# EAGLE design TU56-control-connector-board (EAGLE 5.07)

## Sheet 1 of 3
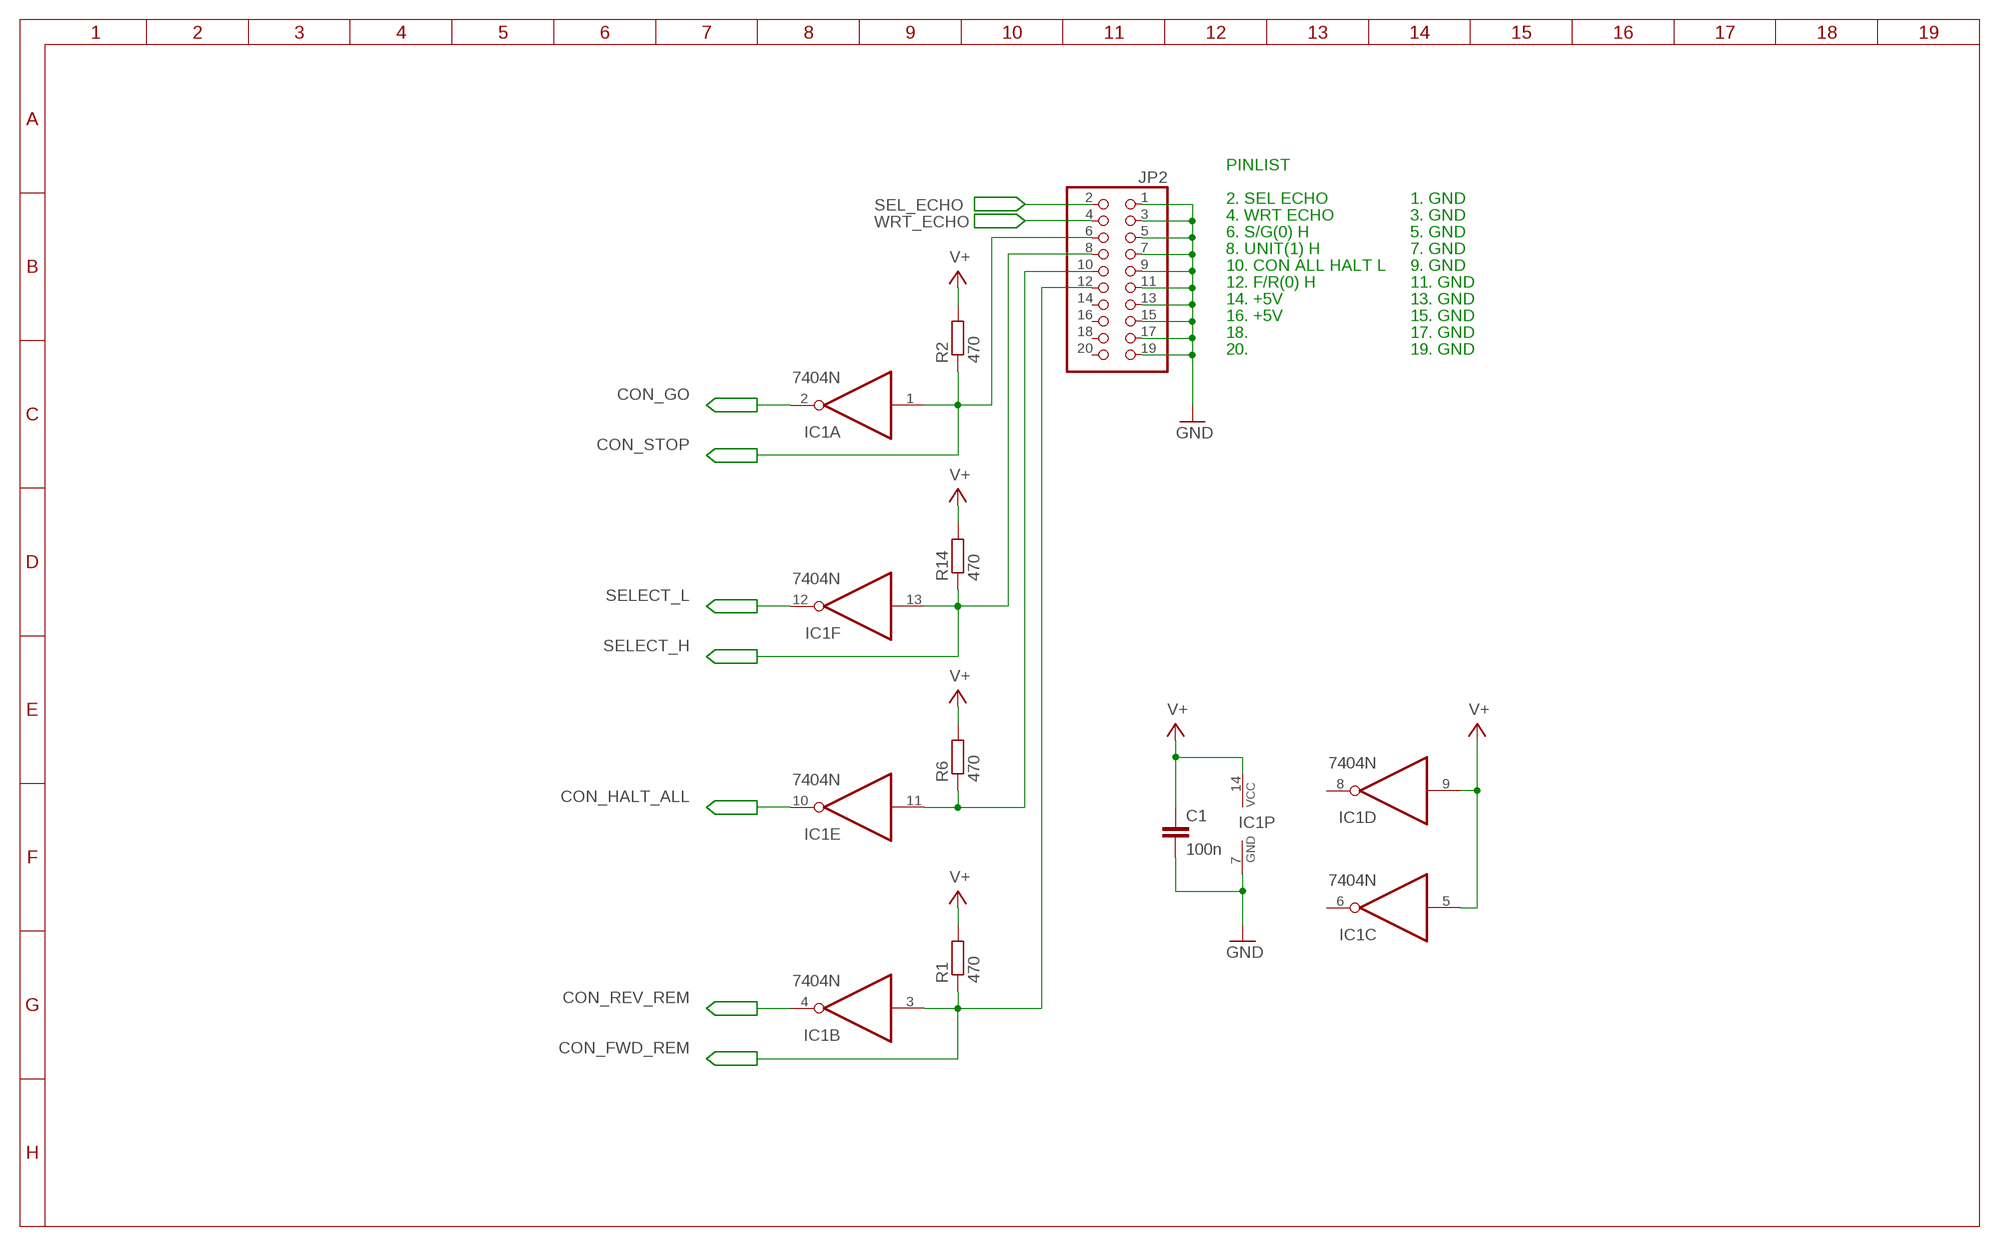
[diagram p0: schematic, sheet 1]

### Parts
C1  100n  C5/3.5  [C5B3.5]
IC1  7404N  [DIL14]
JP2  PINHD-2X10/90-FRAMED  [2Z10/90-FRAMED]
R1  470  R-EU_0207/10  [0207/10]
R2  470  R-EU_0207/10  [0207/10]
R6  470  R-EU_0207/10  [0207/10]
R14  470  R-EU_0207/10  [0207/10]

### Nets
CON_FWD_REM: IC1.3(B:I) JP2.12 R1.1 ; also sheet 3
CON_GO: IC1.2(A:O) ; also sheet 3
CON_HALT_ALL: IC1.10(E:O) ; also sheet 3
CON_REV_REM: IC1.4(B:O) ; also sheet 3
CON_STOP: IC1.1(A:I) JP2.6 R2.1 ; also sheet 3
GND: C1.2 IC1.7(P:GND) JP2.1 JP2.3 JP2.5 JP2.7 JP2.9 JP2.11 JP2.13 JP2.15 JP2.17 JP2.19 ; also sheet 3
N$4: IC1.11(E:I) JP2.10 R6.1
SEL_ECHO: JP2.2 ; also sheet 3
SELECT_H: IC1.13(F:I) JP2.8 R14.1 ; also sheet 2
SELECT_L: IC1.12(F:O) ; also sheet 2
V+: C1.1 IC1.5(C:I) IC1.9(D:I) IC1.14(P:VCC) R1.2 R2.2 R6.2 R14.2 ; also sheet 2,3
WRT_ECHO: JP2.4 ; also sheet 3
Unconnected: IC1.6(C:O) IC1.8(D:O) JP2.14 JP2.16 JP2.18 JP2.20

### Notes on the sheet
- PINLIST
- 2. SEL ECHO | 1. GND
- 4. WRT ECHO | 3. GND
- 6. S/G(0) H | 5. GND
- 8. UNIT(1) H | 7. GND
- 10. CON ALL HALT L | 9. GND
- 12. F/R(0) H | 11. GND
- 14. +5V | 13. GND
- 16. +5V | 15. GND
- 18. | 17. GND
- 20. | 19. GND

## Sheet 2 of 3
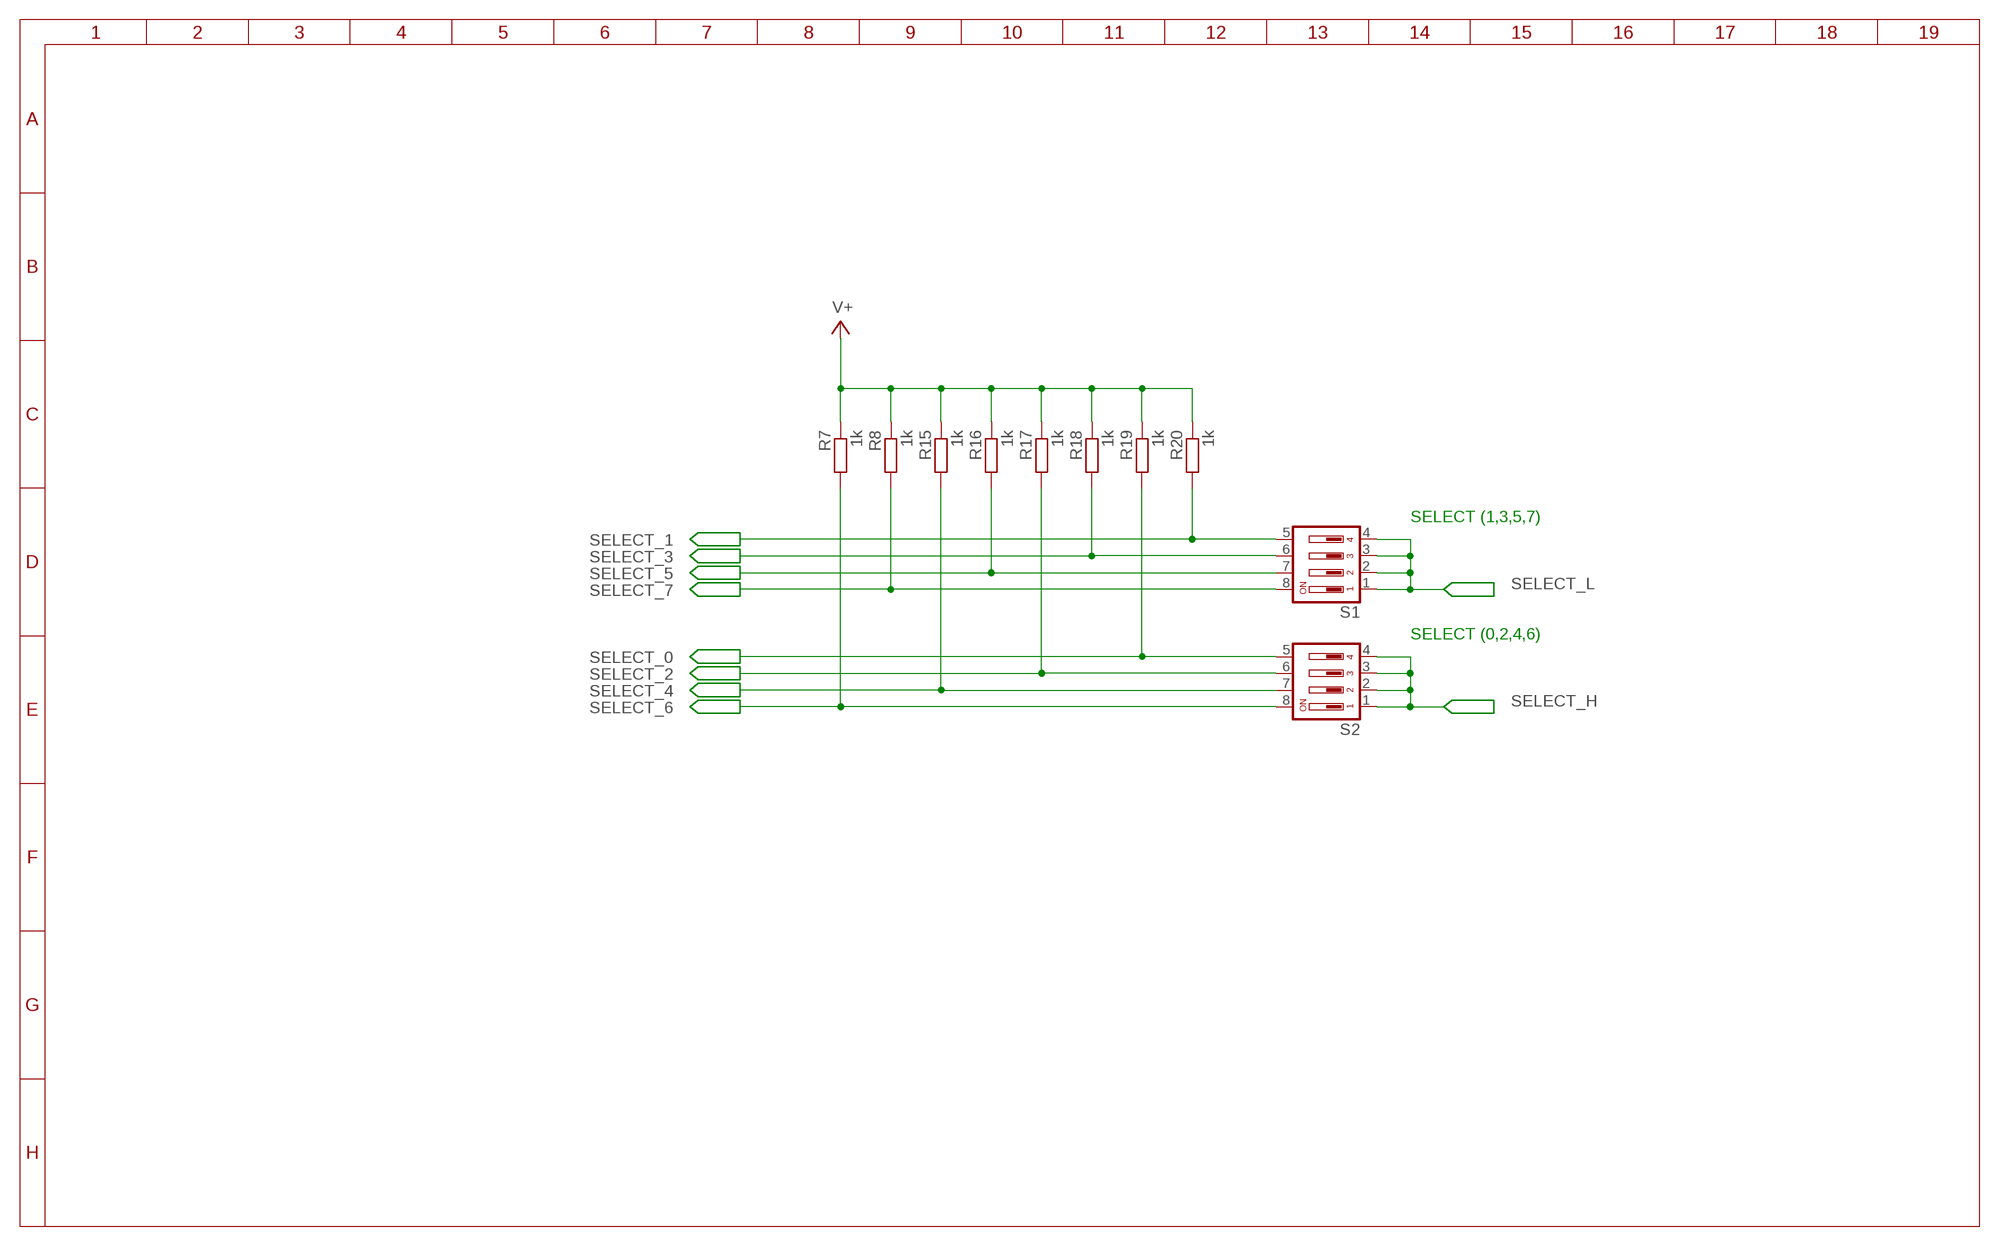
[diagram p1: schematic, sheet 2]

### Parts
R7  1k  R-EU_0207/10  [0207/10]
R8  1k  R-EU_0207/10  [0207/10]
R15  1k  R-EU_0207/10  [0207/10]
R16  1k  R-EU_0207/10  [0207/10]
R17  1k  R-EU_0207/10  [0207/10]
R18  1k  R-EU_0207/10  [0207/10]
R19  1k  R-EU_0207/10  [0207/10]
R20  1k  R-EU_0207/10  [0207/10]
S1  DIP04YL  [DIP04YL]
S2  DIP04YL  [DIP04YL]

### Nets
SELECT_0: R19.2 S2.5 ; also sheet 3
SELECT_1: R20.2 S1.5 ; also sheet 3
SELECT_2: R17.2 S2.6 ; also sheet 3
SELECT_3: R18.2 S1.6 ; also sheet 3
SELECT_4: R15.2 S2.7 ; also sheet 3
SELECT_5: R16.2 S1.7 ; also sheet 3
SELECT_6: R7.2 S2.8 ; also sheet 3
SELECT_7: R8.2 S1.8 ; also sheet 3
SELECT_H: S2.1 S2.2 S2.3 S2.4 ; also sheet 1
SELECT_L: S1.1 S1.2 S1.3 S1.4 ; also sheet 1
V+: R7.1 R8.1 R15.1 R16.1 R17.1 R18.1 R19.1 R20.1 ; also sheet 1,3

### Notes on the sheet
- SELECT (1,3,5,7)
- SELECT (0,2,4,6)

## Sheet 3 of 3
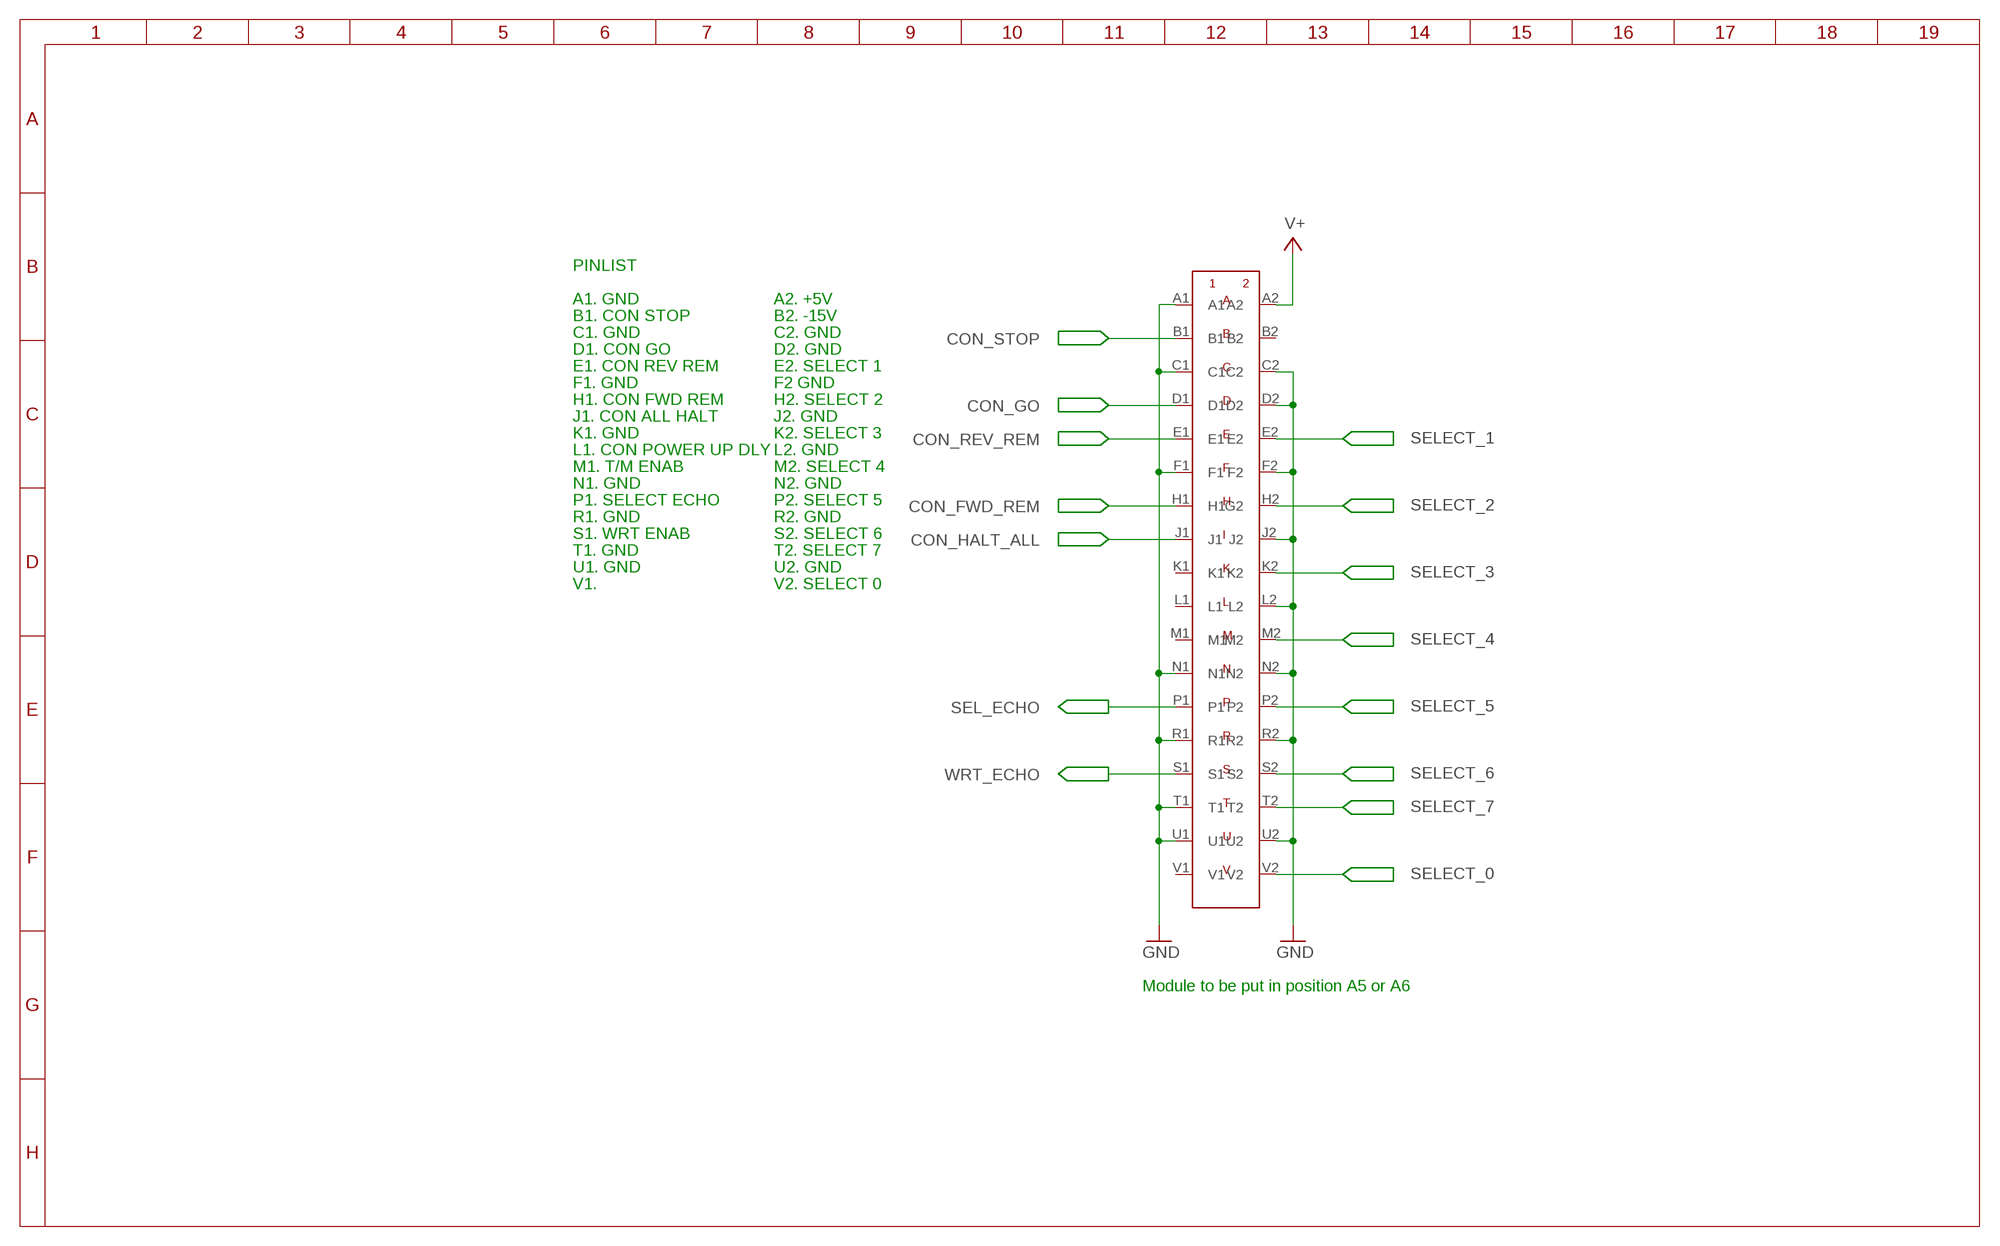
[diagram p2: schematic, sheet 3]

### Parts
CON1  FLIPCHIP_1NORMAL  [FLIPCHIP-1]

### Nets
CON_FWD_REM: CON1.H1 ; also sheet 1
CON_GO: CON1.D1 ; also sheet 1
CON_HALT_ALL: CON1.J1 ; also sheet 1
CON_REV_REM: CON1.E1 ; also sheet 1
CON_STOP: CON1.B1 ; also sheet 1
GND: CON1.A1 CON1.C1 CON1.C2 CON1.D2 CON1.F1 CON1.F2 CON1.J2 CON1.L2 CON1.N1 CON1.N2 CON1.R1 CON1.R2 CON1.T1 CON1.U1 CON1.U2 ; also sheet 1
SEL_ECHO: CON1.P1 ; also sheet 1
SELECT_0: CON1.V2 ; also sheet 2
SELECT_1: CON1.E2 ; also sheet 2
SELECT_2: CON1.H2(G2) ; also sheet 2
SELECT_3: CON1.K2 ; also sheet 2
SELECT_4: CON1.M2 ; also sheet 2
SELECT_5: CON1.P2 ; also sheet 2
SELECT_6: CON1.S2 ; also sheet 2
SELECT_7: CON1.T2 ; also sheet 2
V+: CON1.A2 ; also sheet 1,2
WRT_ECHO: CON1.S1 ; also sheet 1
Unconnected: CON1.B2 CON1.K1 CON1.L1 CON1.M1 CON1.V1

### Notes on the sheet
- PINLIST
- A1. GND | A2. +5V
- B1. CON STOP | B2. -15V
- C1. GND | C2. GND
- D1. CON GO | D2. GND
- E1. CON REV REM | E2. SELECT 1
- F1. GND | F2 GND
- H1. CON FWD REM | H2. SELECT 2
- J1. CON ALL HALT | J2. GND
- K1. GND | K2. SELECT 3
- L1. CON POWER UP DLY | L2. GND
- M1. T/M ENAB | M2. SELECT 4
- N1. GND | N2. GND
- P1. SELECT ECHO | P2. SELECT 5
- R1. GND | R2. GND
- S1. WRT ENAB | S2. SELECT 6
- T1. GND | T2. SELECT 7
- U1. GND | U2. GND
- V1. | V2. SELECT 0
- Module to be put in position A5 or A6

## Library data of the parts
C1 = anders:C: CAPACITOR
CON1 = anders:FLIPCHIP_1: DEC Digital equipment single flipchip
IC1 = 74xx-eu:74*04: Hex INVERTER
JP2 = pinhead:PINHD-2X10: PIN HEADER
R1 R2 R6-R8 R14-R20 = anders:R-EU_: RESISTOR, European symbol
S1 S2 = switch-dil:DIP04YL: DIL/CODE SWITCH

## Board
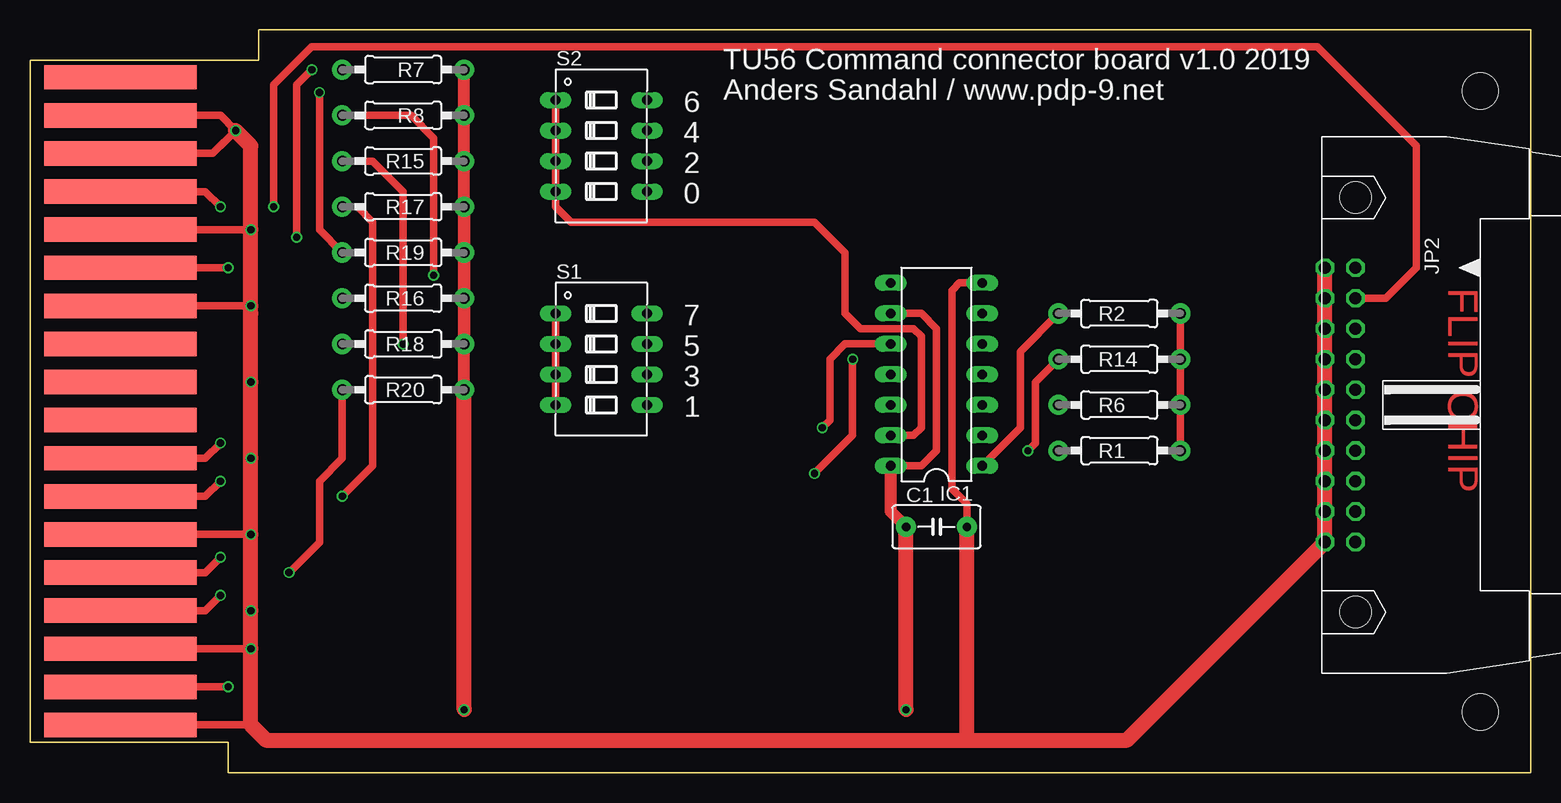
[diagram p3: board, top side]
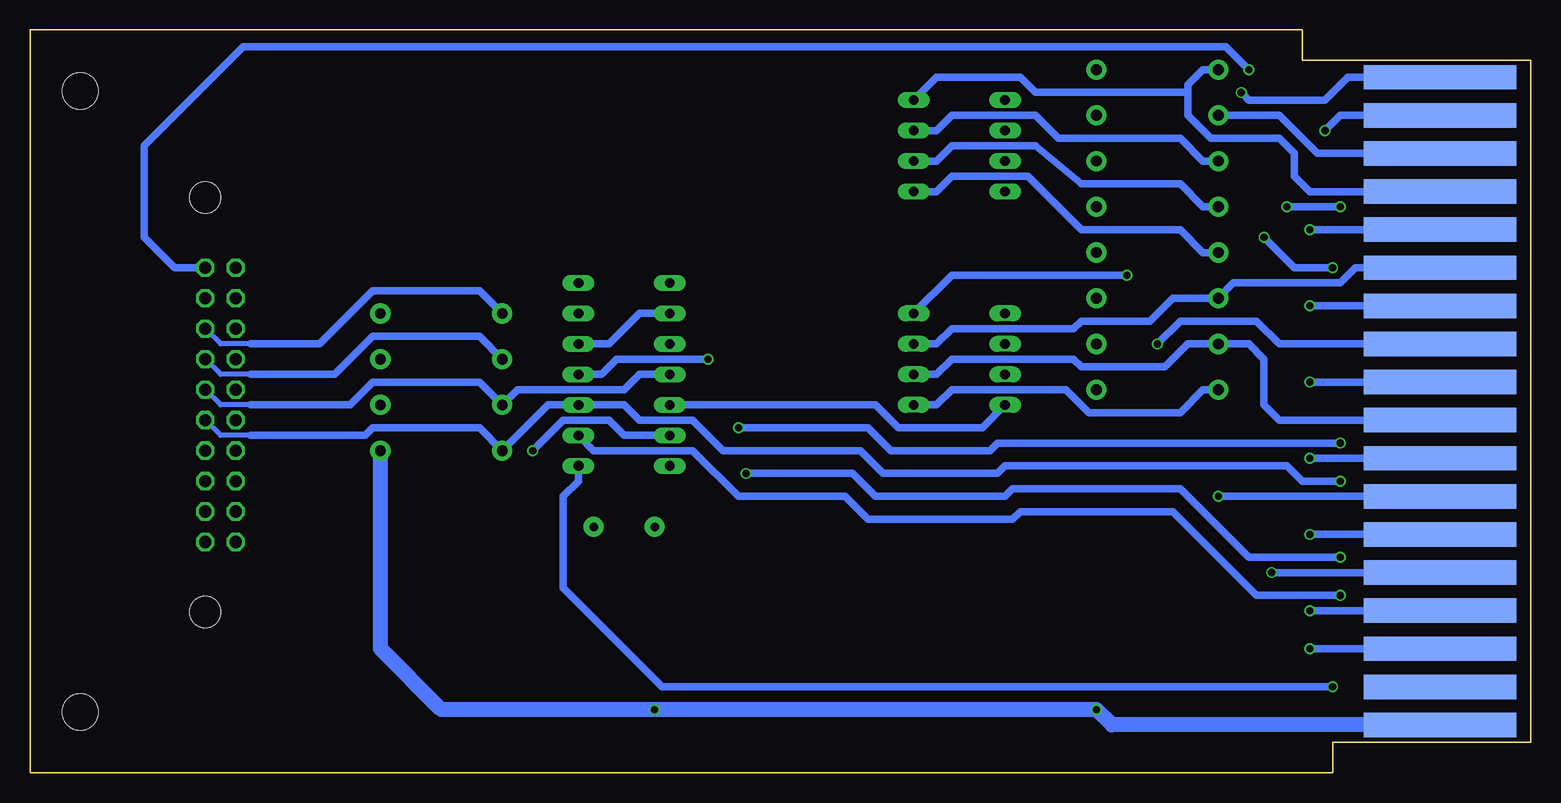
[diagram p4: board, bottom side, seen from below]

Size 125.09 x 61.91 mm. Coordinates in mm from the lower left corner, seen from the top.
Copper layers (1*16): Top 0.035mm / dielectric 1.5mm / Bottom 0.035mm
Design rules "SeeedStudio_2layer_DRU_no_angle_20140221": minimum track width 6mil, minimum drill 12mil, track to track 6mil, track to pad 6mil, pad to pad 6mil, via to via 6mil, smd to smd 0mil, copper to edge 10mil, drill to drill 10mil, minimum pad ring 10mil, minimum via ring 6mil, stop-mask expansion 2mil, vias tented up to drill 100mil, thermal gap 10mil

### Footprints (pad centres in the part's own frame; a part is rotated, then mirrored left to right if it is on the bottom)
C5B3.5 = drill 0.7 pad 1.676 round: 1 -2.54,0; 2 2.54,0
FLIPCHIP-1 = smd 12.7 x 2.032: A1 0.572,0; B1 0.572,3.175; C1 0.572,6.35; D1 0.572,9.525; E1 0.572,12.7; F1 0.572,15.875; H1 0.572,19.05; J1 0.572,22.225; K1 0.572,25.4; L1 0.572,28.575; M1 0.572,31.75; N1 0.572,34.925; P1 0.572,38.1; R1 0.572,41.275; S1 0.572,44.45; T1 0.572,47.625; U1 0.572,50.8; V1 0.572,53.975 | smd 12.7 x 2.032 bottom: A2 0.572,0; B2 0.572,3.175; C2 0.572,6.35; D2 0.572,9.525; E2 0.572,12.7; F2 0.572,15.875; H2 0.572,19.05; J2 0.572,22.225; K2 0.572,25.4; L2 0.572,28.575; M2 0.572,31.75; N2 0.572,34.925; P2 0.572,38.1; R2 0.572,41.275; S2 0.572,44.45; T2 0.572,47.625; U2 0.572,50.8; V2 0.572,53.975 | hole 3: 113.919,52.832; 113.919,1.079
DIL14 = drill 0.813 long: 1 -7.62,-3.81; 2 -5.08,-3.81; 3 -2.54,-3.81; 4 0,-3.81; 5 2.54,-3.81; 6 5.08,-3.81; 7 7.62,-3.81; 8 7.62,3.81; 9 5.08,3.81; 10 2.54,3.81; 11 0,3.81; 12 -2.54,3.81; 13 -5.08,3.81; 14 -7.62,3.81
2Z10/90-FRAMED = drill 1.016 octagon: 1 -11.43,-6.35; 2 -11.43,-3.81; 3 -8.89,-6.35; 4 -8.89,-3.81; 5 -6.35,-6.35; 6 -6.35,-3.81; 7 -3.81,-6.35; 8 -3.81,-3.81; 9 -1.27,-6.35; 10 -1.27,-3.81; 11 1.27,-6.35; 12 1.27,-3.81; 13 3.81,-6.35; 14 3.81,-3.81; 15 6.35,-6.35; 16 6.35,-3.81; 17 8.89,-6.35; 18 8.89,-3.81; 19 11.43,-6.35; 20 11.43,-3.81 | hole 2.6: 17.272,-3.81; -17.272,-3.81
0207/10 = drill 0.9 pad 1.676 round: 1 -5.08,0; 2 5.08,0
DIP04YL = drill 0.813 long: 1 -3.81,-3.81; 2 -1.27,-3.81; 3 1.27,-3.81; 4 3.81,-3.81; 5 3.81,3.81; 6 1.27,3.81; 7 -1.27,3.81; 8 -3.81,3.81

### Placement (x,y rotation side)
C1  75.56,20.51 0 top
CON1  6.99,4 0 top
IC1  75.56,33.21 90 top
JP2  114.3,30.67 270 top
R1  90.8,26.86 0 top
R2  90.8,38.29 0 top
R6  90.8,30.67 0 top
R7  31.12,58.61 180 top
R8  31.12,54.8 180 top
R14  90.8,34.48 0 top
R15  31.12,50.99 180 top
R16  31.12,39.56 180 top
R17  31.12,47.18 180 top
R18  31.12,35.75 180 top
R19  31.12,43.37 180 top
R20  31.12,31.94 180 top
S1  47.62,34.48 270 top
S2  47.62,52.26 270 top

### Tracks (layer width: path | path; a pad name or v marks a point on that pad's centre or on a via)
CON_FWD_REM  (via drill 0.6)
  Top 0.61: CON1.H1 14.61,23.05 v15.88,24.32
  Bottom 0.406: JP2.12 109.22,28.13 106.68,28.13
  Bottom 0.61: 106.68,28.13 97.16,28.13 96.52,28.77 87.63,28.77 R1.1 81.91,30.67 IC1.3 75.56,30.67 74.3,29.4 69.85,29.4 67.31,26.86 55.88,26.86 53.98,24.96 44.45,24.96 43.82,25.59 20.32,25.59 19.05,24.32 v15.88,24.32
CON_GO  (via drill 0.6)
  Top 0.61: CON1.D1 14.61,13.53 v15.88,14.8
  Bottom 0.61: v15.88,14.8 22.86,14.8 29.84,21.78 42.55,21.78 43.18,21.15 55.25,21.15 57.15,23.05 66.04,23.05 69.85,26.86 78.1,26.86 IC1.2
CON_HALT_ALL  (via drill 0.6)
  Top 0.61: CON1.J1 14.61,26.23 v15.88,27.5 | v66.04,28.77 66.67,29.4 66.67,34.48 67.94,35.75 IC1.10
  Bottom 0.61: v15.88,27.5 44.45,27.5 45.09,26.86 53.34,26.86 55.25,28.77 v66.04,28.77
CON_REV_REM  (via drill 0.6)
  Top 0.61: CON1.E1 14.61,16.7 v15.88,17.97 | v68.58,34.48 68.58,28.13 v65.41,24.96
  Bottom 0.61: v15.88,17.97 23.49,17.97 29.21,23.69 43.18,23.69 43.82,23.05 54.61,23.05 56.52,24.96 v65.41,24.96 | IC1.4 77.47,33.21 76.2,34.48 v68.58,34.48
CON_STOP  (via drill 0.6)
  Top 0.61: R2.1 82.55,35.12 82.55,28.77 IC1.1 | CON1.B1 v16.51,7.18
  Bottom 0.406: 106.68,35.75 109.22,35.75 JP2.6
  Bottom 0.61: R2.1 87.63,40.2 96.52,40.2 100.96,35.75 106.68,35.75 | v16.51,7.18 72.39,7.18 80.64,15.43 80.64,23.05 79.38,24.32 IC1.1
GND  (via drill 0.6)
  Top 0.61: C1.2 78.1,22.42 76.83,23.69 76.83,40.2 77.47,40.83 IC1.7 | CON1.A1 18.41,4 | v18.41,10.35 CON1.C1 | v18.41,19.88 CON1.F1 | v18.41,38.93 CON1.N1 | CON1.R1 v18.41,45.28 18.41,38.29 | CON1.U1 15.88,54.8 v17.15,53.53 | v17.15,53.53 15.24,51.63 CON1.T1 | v17.15,53.53 15.88,52.26
  Top 1.27: JP2.1 JP2.3 JP2.5 JP2.7 JP2.9 JP2.11 JP2.13 JP2.15 JP2.17 JP2.19 91.44,2.73 78.1,2.73 | v17.15,53.53 18.41,52.26 v18.41,45.28 v18.41,38.93 18.41,38.29 v18.41,32.58 v18.41,26.23 v18.41,19.88 v18.41,13.53 v18.41,10.35 18.41,4 19.69,2.73 78.1,2.73 | 78.1,2.73 C1.2
  Bottom 0.61: v18.41,13.53 CON1.D2 | v18.41,10.35 CON1.C1 | v18.41,19.88 CON1.F1 | v18.41,26.23 CON1.J2 | v18.41,32.58 CON1.L2 | v18.41,38.93 CON1.N1 | v18.41,45.28 CON1.R1 | CON1.U1 15.88,54.8 v17.15,53.53
N$4
  Bottom 0.406: JP2.10 109.22,30.67 106.68,30.67
  Bottom 0.61: 106.68,30.67 98.42,30.67 96.52,32.58 87.63,32.58 R6.1 84.45,31.94 75.56,31.94 74.3,33.21 IC1.11
SEL_ECHO  (via drill 0.6)
  Top 0.61: CON1.P1 v16.51,42.1 | v22.23,44.64 22.23,57.34 v23.49,58.61
  Bottom 0.61: JP2.2 113.03,42.1 115.57,44.64 115.57,52.26 107.31,60.52 25.4,60.52 v23.49,58.61 | v16.51,42.1 19.69,42.1 v22.23,44.64
SELECT_0  (via drill 0.6)
  Top 0.61: v24.13,56.71 24.13,45.28 R19.2
  Bottom 0.61: CON1.V2 15.24,57.98 17.15,56.07 23.49,56.07 v24.13,56.71 | R19.2 27.3,43.37 29.21,45.28 37.47,45.28 41.91,49.72 48.26,49.72 49.53,48.45 S2.5
SELECT_1  (via drill 0.6)
  Top 0.61: R20.2 26.04,26.23 24.13,24.32 24.13,19.24 v21.59,16.7
  Bottom 0.61: S1.5 49.53,30.67 48.26,31.94 38.73,31.94 36.83,30.04 29.21,30.04 27.3,31.94 R20.2 | CON1.E2 v21.59,16.7
SELECT_2  (via drill 0.6)
  Top 0.61: R17.2 27.3,47.18 28.58,45.91 28.58,25.59 v26.04,23.05
  Bottom 0.61: S2.6 49.53,50.99 48.26,52.26 41.27,52.26 37.47,49.09 29.21,49.09 27.3,47.18 R17.2 | CON1.H2 v26.04,23.05
SELECT_3
  Bottom 0.61: S1.6 49.53,33.21 48.26,34.48 38.1,34.48 37.47,33.85 30.48,33.85 28.58,35.75 R18.2 23.49,35.75 22.23,34.48 22.23,30.67 20.95,29.4 CON1.K2
SELECT_4  (via drill 0.6)
  Top 0.61: v31.12,35.75 31.12,48.45 28.58,50.99 R15.2
  Bottom 0.61: R15.2 27.3,50.99 29.21,52.9 39.37,52.9 41.27,54.8 48.26,54.8 49.53,53.53 S2.7 | CON1.M2 20.95,35.75 22.86,37.66 29.21,37.66 v31.12,35.75
SELECT_5
  Bottom 0.61: CON1.P2 14.61,42.1 15.88,40.83 24.77,40.83 R16.2 29.84,39.56 31.75,37.66 37.47,37.66 38.1,37.02 48.26,37.02 49.53,35.75 S1.7
SELECT_6
  Bottom 0.61: R7.2 27.3,58.61 28.58,57.34 28.58,56.71 | 28.58,56.71 28.58,54.8 26.67,52.9 20.95,52.9 19.69,51.63 19.69,49.72 18.41,48.45 CON1.S2 | S2.8 49.53,57.98 42.55,57.98 41.27,56.71 28.58,56.71
SELECT_7  (via drill 0.6)
  Top 0.61: R8.2 31.75,54.8 33.66,52.9 v33.66,41.47
  Bottom 0.61: CON1.T2 17.78,51.63 20.95,54.8 R8.2 | v33.66,41.47 48.26,41.47 S1.8
SELECT_H  (via drill 0.6)
  Top 0.61: S2.1 S2.2 S2.3 S2.4 43.82,47.18 45.09,45.91 65.41,45.91 67.94,43.37 67.94,38.29 69.21,37.02 73.66,37.02 74.3,36.39 74.3,28.77 73.66,28.13 IC1.13 | R14.1 83.82,32.58 83.82,27.5 v83.18,26.86
  Bottom 0.406: JP2.8 109.22,33.21 106.68,33.21 106.05,33.21
  Bottom 0.61: R14.1 87.63,36.39 96.52,36.39 99.69,33.21 106.68,33.21 | v83.18,26.86 80.64,29.4 76.83,29.4 75.56,28.13 IC1.13
SELECT_L
  Top 0.61: S1.4 S1.3 S1.2 S1.1
  Bottom 0.61: IC1.12 54.61,30.67 52.71,28.77 45.72,28.77 S1.4
V+  (via drill 0.6)
  Top 0.61: R14.2 R2.2 | R14.2 R6.2 R1.2 R14.2 | IC1.14 74.3,25.59 75.56,26.86 75.56,37.02 74.3,38.29 IC1.9
  Top 1.016: IC1.14 71.75,21.78 C1.1 | R7.1 R8.1 R15.1 R16.1 R17.1 R18.1 R19.1 R20.1
  Top 1.27: v36.2,5.27 R20.1 | v73.02,5.27 C1.1
  Bottom 0.61: IC1.5 76.83,35.75 74.3,38.29 IC1.9
  Bottom 1.27: CON1.A2 34.93,4 v36.2,5.27 v73.02,5.27 90.8,5.27 95.88,10.35 R1.2
WRT_ECHO  (via drill 0.6)
  Top 0.61: v20.32,47.18 20.32,57.34 23.49,60.52 107.31,60.52 115.57,52.26 115.57,42.1 113.03,39.56 JP2.4 | CON1.S1 14.61,48.45 v15.88,47.18
  Bottom 0.61: v15.88,47.18 v20.32,47.18

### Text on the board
tNames: TU56 Command connector board v1.0 2019 | Anders Sandahl / www.pdp-9.net | 6 | 4 | 2 | 0 | 7 | 5 | 3 | 1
